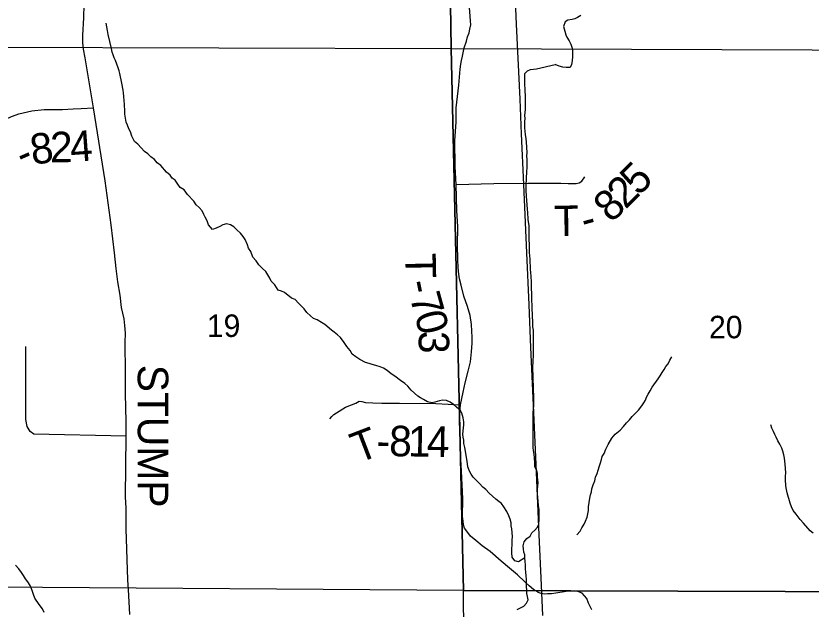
# Model space of a CAD drawing. Extents: x 0 to 34, y 0 to 22.
# Drawn here: x 6.308 to 7.789, y 18.992 to 20.096 of the extents above; entities that cross this region are included whole.
import ezdxf

# ---------------------------------------------------------------- set-up
doc = ezdxf.new("R2010")
doc.units = 0
doc.layers.add('Default', color=7, linetype='Continuous')

msp = doc.modelspace()

# ---------------------------------------------------------------- linework, layer by layer
at = {"layer": 'Default'}
for points in [[(7.1051, 20.9), (6.2451, 20.9), (6.2523, 20.0379), (7.1182, 20.0358)], [(8.1138, 20.9), (7.1051, 20.9), (7.1182, 20.0358), (8.1266, 20.0321)], [(6.2523, 20.0379), (7.1182, 20.0358), (7.1411, 19.0266), (6.2698, 19.0329), (6.2526, 20.0047)], [(7.1182, 20.0358), (8.1266, 20.0321), (8.1392, 19.0236), (7.1411, 19.0266)], [(7.1411, 19.0266), (8.1392, 19.0236), (8.1478, 18.0308), (7.1486, 18.0293)]]:
    msp.add_lwpolyline(points, close=True, dxfattribs=at)
for points in [[(6.5202, 18.9817), (6.5176, 19.0282), (6.5164, 19.0465), (6.5132, 19.1412), (6.5132, 19.1797), (6.5119, 19.2011), (6.5129, 19.3141), (6.5129, 19.3408), (6.5121, 19.393), (6.5121, 19.4325), (6.511, 19.4885), (6.5121, 19.5059), (6.5108, 19.5199), (6.5093, 19.5323), (6.5044, 19.5535), (6.5019, 19.5766), (6.4978, 19.601), (6.4944, 19.6259), (6.4917, 19.6549), (6.4851, 19.7076), (6.4738, 19.7895), (6.4524, 19.9252), (6.4435, 19.9773), (6.4369, 20.0181), (6.4337, 20.0347), (6.4323, 20.046), (6.4323, 20.0605), (6.4341, 20.0925), (6.4356, 20.1428)], [(7.2888, 18.9797), (7.2865, 19.0366), (7.2823, 19.13), (7.2765, 19.2614), (7.271, 19.3853), (7.2669, 19.4791), (7.2636, 19.5584), (7.2591, 19.6551), (7.2535, 19.7826), (7.2493, 19.8769), (7.2466, 19.9413), (7.2402, 20.081), (7.2376, 20.1407)], [(7.38, 18.9903), (7.3743, 19.0031), (7.3709, 19.0114), (7.3669, 19.0166), (7.3623, 19.0216), (7.3543, 19.0245), (7.3453, 19.0253), (7.3326, 19.0245), (7.3133, 19.0217), (7.3051, 19.0205), (7.2977, 19.0201), (7.2922, 19.0198), (7.2861, 19.0209), (7.2806, 19.0227), (7.2774, 19.0251), (7.2717, 19.0286), (7.2636, 19.0355), (7.2555, 19.0424), (7.2419, 19.0555), (7.2268, 19.0679), (7.2112, 19.0812), (7.191, 19.099), (7.1763, 19.1097), (7.1641, 19.1195), (7.1541, 19.1276), (7.1491, 19.1344), (7.143, 19.1424), (7.1412, 19.1485), (7.1406, 19.1557), (7.1397, 19.1641), (7.1403, 19.1972), (7.1378, 19.2488), (7.1354, 19.2923), (7.1348, 19.3102), (7.1346, 19.3279), (7.1341, 19.3386), (7.1343, 19.3511), (7.1347, 19.3592), (7.1358, 19.372), (7.1405, 19.3956), (7.1443, 19.4129), (7.15, 19.4347), (7.1545, 19.4521), (7.1565, 19.4708), (7.1576, 19.4873), (7.1573, 19.498), (7.1568, 19.5091), (7.1562, 19.5215), (7.1537, 19.5388), (7.149, 19.555), (7.1422, 19.5746), (7.1372, 19.5951), (7.1341, 19.6071), (7.1326, 19.6155), (7.1316, 19.6271), (7.131, 19.6437), (7.1303, 19.6687), (7.1305, 19.7042), (7.1288, 19.7336), (7.1275, 19.7827), (7.1259, 19.8151), (7.1254, 19.8643), (7.1275, 19.8983), (7.1278, 19.9249), (7.1326, 19.9675), (7.1354, 19.9972), (7.1366, 20.0065), (7.1378, 20.0131), (7.1394, 20.0213), (7.1411, 20.0306), (7.1427, 20.0369), (7.147, 20.0496), (7.149, 20.0573), (7.1516, 20.0648), (7.1533, 20.0718), (7.1547, 20.0794), (7.1546, 20.087), (7.1519, 20.1209)], [(7.3597, 20.0969), (7.3536, 20.0935), (7.3487, 20.0908), (7.3438, 20.0896), (7.3358, 20.0884), (7.3305, 20.085), (7.3275, 20.0766), (7.3298, 20.0679), (7.3318, 20.0614), (7.3337, 20.0565), (7.3379, 20.0497), (7.341, 20.0436), (7.3441, 20.0345), (7.3445, 20.0266), (7.3442, 20.0205), (7.3434, 20.0129), (7.3423, 20.0057), (7.3401, 20.0003), (7.3325, 20.0003), (7.3264, 20.001), (7.3192, 20.0029), (7.312, 20.0059)], [(6.7493, 19.6473), (6.745, 19.6579), (6.7407, 19.6636), (6.7391, 19.6704), (6.7345, 19.6803), (6.731, 19.6855), (6.726, 19.692), (6.7194, 19.6983), (6.7137, 19.7036), (6.7075, 19.7073), (6.6999, 19.7091), (6.6931, 19.7071), (6.6878, 19.7044), (6.681, 19.7009), (6.6742, 19.6985), (6.6665, 19.7071), (6.6637, 19.7147), (6.6602, 19.7215), (6.6579, 19.7268), (6.6544, 19.7332), (6.649, 19.7396), (6.6436, 19.7445), (6.6394, 19.7513), (6.6271, 19.7641), (6.6213, 19.7728), (6.614, 19.7768), (6.6093, 19.7829), (6.6047, 19.7904), (6.599, 19.7942), (6.5951, 19.7998), (6.5882, 19.8054), (6.5774, 19.8175), (6.5709, 19.8227), (6.5659, 19.8287), (6.559, 19.834), (6.5532, 19.8396), (6.5471, 19.8441), (6.5347, 19.8576), (6.5286, 19.8625), (6.5239, 19.8727), (6.5212, 19.8807), (6.5181, 19.8863), (6.5157, 19.8932), (6.5134, 19.8984), (6.5118, 19.906), (6.5109, 19.9136), (6.5109, 19.919), (6.51, 19.9311), (6.509, 19.946), (6.5082, 19.9528), (6.5074, 19.9581), (6.5049, 19.9714), (6.5037, 19.9775), (6.5029, 19.9828), (6.5013, 19.9889), (6.5001, 19.9942), (6.4981, 19.9999), (6.4931, 20.0131), (6.4911, 20.0184), (6.4888, 20.0237), (6.4872, 20.029), (6.486, 20.0355), (6.4796, 20.0617), (6.4784, 20.0689), (6.4759, 20.0826)], [(7.2741, 19.1386), (7.2793, 19.1444), (7.2816, 19.1498), (7.2822, 19.1589), (7.282, 19.1776), (7.2812, 19.1848), (7.2803, 19.1931), (7.2795, 19.2), (7.279, 19.2057), (7.2793, 19.2137), (7.28, 19.2217), (7.2803, 19.227), (7.2799, 19.2327), (7.2794, 19.2388), (7.279, 19.2441), (7.2781, 19.2502), (7.2743, 19.2566), (7.2742, 19.2639), (7.2737, 19.2734), (7.2729, 19.2802), (7.2716, 19.2871), (7.2712, 19.2924), (7.271, 19.3137), (7.2713, 19.3194), (7.2711, 19.3365), (7.271, 19.3442), (7.2709, 19.3514), (7.2712, 19.3575), (7.2719, 19.3647), (7.2722, 19.3704), (7.2725, 19.3803), (7.272, 19.3857), (7.2718, 19.4024), (7.2714, 19.4096), (7.2713, 19.4169), (7.2709, 19.4222), (7.2706, 19.4435), (7.2709, 19.4519), (7.2715, 19.4667), (7.2718, 19.4763), (7.2717, 19.485), (7.2719, 19.4972), (7.2715, 19.5029), (7.2714, 19.5113), (7.2705, 19.5174), (7.2701, 19.5227), (7.2699, 19.5417), (7.2694, 19.5497), (7.2693, 19.5565), (7.2685, 19.5676), (7.2681, 19.6003), (7.2676, 19.6117), (7.2668, 19.6178), (7.2663, 19.6247), (7.2653, 19.6433), (7.2644, 19.6558), (7.2644, 19.6619), (7.2639, 19.6684), (7.2637, 19.6825), (7.2636, 19.6939), (7.2635, 19.7053), (7.2618, 19.7171), (7.2609, 19.7308), (7.2605, 19.7361), (7.26, 19.7449), (7.2591, 19.7521), (7.2583, 19.762), (7.2578, 19.77), (7.2577, 19.7772), (7.258, 19.7829), (7.2583, 19.7909), (7.2586, 19.7962), (7.2593, 19.8042), (7.2599, 19.8164), (7.2598, 19.829), (7.2593, 19.8355), (7.2597, 19.8415), (7.2583, 19.8621), (7.2582, 19.8674), (7.2566, 19.8758), (7.2557, 19.8879), (7.2556, 19.8936), (7.2556, 19.8997), (7.2559, 19.9055), (7.2558, 19.9112), (7.2565, 19.9222), (7.2568, 19.9298), (7.2565, 19.9492), (7.2561, 19.9549), (7.256, 19.9603), (7.2556, 19.9679), (7.2554, 19.9831), (7.2557, 19.9888), (7.2606, 19.9942), (7.2663, 19.9966), (7.2773, 19.9975), (7.312, 20.0059)], [(6.2434, 19.8932), (6.2772, 19.8988), (6.2903, 19.9047), (6.2999, 19.9091), (6.3082, 19.9123), (6.3131, 19.9138), (6.3212, 19.9159)], [(6.3212, 19.9159), (6.3378, 19.9196), (6.3607, 19.9223), (6.3947, 19.9221), (6.4142, 19.9233), (6.4291, 19.924), (6.4524, 19.9252)], [(7.1275, 19.7827), (7.1977, 19.7843), (7.2609, 19.7849), (7.3223, 19.7849), (7.336, 19.7846), (7.3445, 19.7843), (7.3512, 19.7842), (7.3567, 19.7855), (7.3614, 19.7888), (7.3674, 19.7966)], [(7.2553, 19.0874), (7.2436, 19.08), (7.2371, 19.0818), (7.2321, 19.0886), (7.2316, 19.0966), (7.2315, 19.1023), (7.2321, 19.1137), (7.2321, 19.1209), (7.2324, 19.1263), (7.2319, 19.1343), (7.2311, 19.1415), (7.2303, 19.1468), (7.2298, 19.1525), (7.2282, 19.1593), (7.2259, 19.1658), (7.222, 19.1733), (7.2165, 19.1824), (7.2123, 19.1884), (7.2069, 19.1925), (7.2016, 19.1963), (7.1889, 19.2079), (7.1827, 19.2147), (7.177, 19.2188), (7.1712, 19.2256), (7.1646, 19.2319), (7.1593, 19.2376), (7.1558, 19.2432), (7.1527, 19.2489), (7.1495, 19.2569), (7.1479, 19.2675), (7.1471, 19.2743), (7.1454, 19.2823), (7.1438, 19.2929), (7.1422, 19.3005), (7.1418, 19.3062), (7.1405, 19.3119), (7.1401, 19.3176), (7.1415, 19.3295), (7.1418, 19.3348), (7.1417, 19.3405), (7.1409, 19.3481), (7.1381, 19.3564), (7.135, 19.3621), (7.1285, 19.3681), (7.1224, 19.373), (7.1162, 19.3771), (7.1094, 19.3804), (7.1021, 19.3807), (7.0968, 19.3799), (7.0881, 19.3771), (7.0824, 19.3759), (7.0744, 19.3777), (7.0667, 19.3821), (7.0614, 19.3855), (7.056, 19.3881), (7.0499, 19.3937), (7.0437, 19.3997), (7.0376, 19.4069), (7.0318, 19.4121), (7.0241, 19.4173), (7.0134, 19.4256), (7.0069, 19.43), (6.9992, 19.436), (6.9923, 19.4405), (6.9862, 19.4431), (6.9778, 19.4453), (6.9713, 19.4471), (6.9656, 19.4489), (6.9591, 19.4511), (6.948, 19.4566), (6.9407, 19.4615), (6.9338, 19.4667), (6.93, 19.4732), (6.9242, 19.4807), (6.9192, 19.4882), (6.9122, 19.4973), (6.9068, 19.5025), (6.9007, 19.5074), (6.8953, 19.5115), (6.883, 19.522), (6.8769, 19.5257), (6.8685, 19.5302), (6.862, 19.5331), (6.8562, 19.538), (6.8497, 19.5444), (6.8443, 19.5508), (6.8393, 19.5564), (6.8343, 19.5617), (6.8278, 19.5681), (6.8213, 19.571), (6.8078, 19.5815), (6.8021, 19.5841), (6.796, 19.5855), (6.7902, 19.5954), (6.7833, 19.6025), (6.7805, 19.6078), (6.7732, 19.6203), (6.767, 19.6259), (6.7601, 19.633), (6.7551, 19.6406), (6.7493, 19.6473)], [(6.5129, 19.3141), (6.3414, 19.3174), (6.3346, 19.3225), (6.3291, 19.3319), (6.3261, 19.3446), (6.3265, 19.4809)], [(7.3521, 19.1302), (7.3585, 19.1371), (7.3619, 19.1429), (7.3663, 19.1498), (7.3686, 19.1555), (7.3715, 19.1628), (7.374, 19.1754), (7.3743, 19.1822), (7.3754, 19.1906), (7.3768, 19.1983), (7.3775, 19.2044), (7.3794, 19.2105), (7.3804, 19.2158), (7.3826, 19.2235), (7.3856, 19.2307), (7.3874, 19.2376), (7.3904, 19.2445), (7.3922, 19.2506), (7.3948, 19.2587), (7.3962, 19.264), (7.3984, 19.2705), (7.3995, 19.2758), (7.4033, 19.2816), (7.4066, 19.2896), (7.4107, 19.2981), (7.4178, 19.3104), (7.4238, 19.3173), (7.4332, 19.325), (7.4392, 19.332), (7.4448, 19.3385), (7.4505, 19.3443), (7.4553, 19.3505), (7.461, 19.3559), (7.467, 19.3624), (7.4734, 19.3701), (7.4771, 19.3759), (7.4801, 19.3812), (7.4823, 19.3866), (7.4853, 19.392), (7.4886, 19.3985), (7.4927, 19.4054), (7.5036, 19.4204), (7.5077, 19.4265), (7.5111, 19.4323), (7.5148, 19.4377), (7.5178, 19.4434), (7.5227, 19.4488), (7.5256, 19.4553), (7.529, 19.4618)], [(6.8926, 19.3459), (6.896, 19.3502), (6.9, 19.354), (6.905, 19.3575), (6.9217, 19.3676), (6.933, 19.3722), (6.9407, 19.3754), (6.9471, 19.3791), (6.952, 19.3783), (6.959, 19.3764), (6.9725, 19.3762), (6.9895, 19.3756), (7.0223, 19.3754), (7.0897, 19.3744), (7.1358, 19.372)], [(7.7924, 19.1335), (7.7871, 19.1376), (7.7743, 19.1519), (7.7682, 19.1586), (7.7608, 19.1688), (7.7554, 19.1756), (7.7523, 19.1824), (7.7496, 19.1892), (7.7437, 19.2086), (7.7425, 19.2143), (7.7416, 19.2211), (7.7407, 19.2329), (7.741, 19.2397), (7.7417, 19.2455), (7.7412, 19.2534), (7.74, 19.2618), (7.7391, 19.2732), (7.7379, 19.2793), (7.7359, 19.2857), (7.734, 19.2918), (7.7305, 19.299), (7.7266, 19.305), (7.7235, 19.3118), (7.7211, 19.3171), (7.7188, 19.3228), (7.7157, 19.3289), (7.7133, 19.3349)], [(7.2411, 18.9912), (7.2472, 18.994), (7.2536, 18.9971), (7.2589, 19.0029), (7.2615, 19.009), (7.2603, 19.0155), (7.2594, 19.0212), (7.2594, 19.028), (7.2589, 19.0334), (7.2588, 19.0413), (7.2588, 19.0471), (7.2579, 19.0543), (7.2571, 19.06), (7.2566, 19.0676), (7.2565, 19.0744), (7.2561, 19.0805), (7.2553, 19.0874), (7.2552, 19.0927), (7.2536, 19.098), (7.2528, 19.1041), (7.2523, 19.1098), (7.2545, 19.117), (7.2594, 19.1236), (7.2655, 19.1275), (7.2688, 19.1336), (7.2741, 19.1386)], [(6.3606, 18.9858), (6.3575, 18.9926), (6.3509, 19.0005), (6.3432, 19.0122), (6.3408, 19.019), (6.3381, 19.0266), (6.3345, 19.0357), (6.3303, 19.0425), (6.3256, 19.0485), (6.3218, 19.0542), (6.3183, 19.0598), (6.3133, 19.0666), (6.3071, 19.0738)]]:
    msp.add_lwpolyline(points, dxfattribs=at)

# ---------------------------------------------------------------- texts
for s, height, rotation, p in [('8', 0.0568, 8.3715, (6.3388, 19.8188)), ('2', 0.0568, 0.5256, (6.3714, 19.8237)), ('4', 0.0568, 4.1845, (6.4103, 19.8242)), ('-', 0.0568, 23.7875, (6.3213, 19.8105)), ('5', 0.0568, 45.2568, (7.4675, 19.7596)), ('2', 0.0568, 45.3059, (7.4431, 19.735)), ('8', 0.0568, 43.2142, (7.4162, 19.7096)), ('T', 0.0568, 1.0297, (7.3101, 19.686)), ('-', 0.0568, 15.1151, (7.3676, 19.6889)), ('T', 0.0568, 271.17, (7.0328, 19.654)), ('-', 0.0568, 281.7378, (7.035, 19.6002)), ('7', 0.0568, 285.4062, (7.0407, 19.5735)), ('0', 0.0568, 284.4162, (7.0499, 19.54)), ('19', 0.04186, 0, (6.6635, 19.4986)), ('20', 0.04186, 0, (7.5985, 19.4961)), ('3', 0.0568, 269.4692, (7.0581, 19.51)), ('STUMP', 0.05682, 270, (6.5347, 19.4469)), ('T', 0.0568, 20.9252, (6.945, 19.2629)), ('8', 0.0568, 359.0888, (7.0025, 19.2767)), ('1', 0.0568, 359.0975, (7.0375, 19.2762)), ('4', 0.0568, 359.1043, (7.0725, 19.2756)), ('-', 0.0568, 359.0476, (6.9791, 19.2771))]:
    msp.add_text(s, height=height, rotation=rotation, dxfattribs=at).set_placement(p)

doc.saveas('drawing.dxf')
